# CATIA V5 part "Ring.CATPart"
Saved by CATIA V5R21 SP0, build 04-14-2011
Part number: Part1.1
Bounding box of the stored display mesh (mm): x -5 to 5, y -15 to 15, z -15 to 15
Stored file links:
  D:\CATIA V5R21 E-RESOURCES\CATIA-V5R21\catia-v5r21-Prts\c12-catia-v5r21-prt\c12_catia_v5r21figr_12-15\Ring_cat_v5r21.CATPart
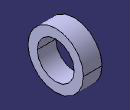
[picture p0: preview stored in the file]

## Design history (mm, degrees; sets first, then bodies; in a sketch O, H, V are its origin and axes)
Body1 (main body)
  Sketch1 on yz-plane, origin (0, 0, 0), H (0, 1, 0), V (0, 0, 1)
    circle A1 centre (0, 0) radius 15
    circle A2 centre (0, 0) radius 10
    radius A1 = 15
    radius A2 = 10
  Pad1: profile Sketch1, direction (1, 0, 0), length 5, mirrored extent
